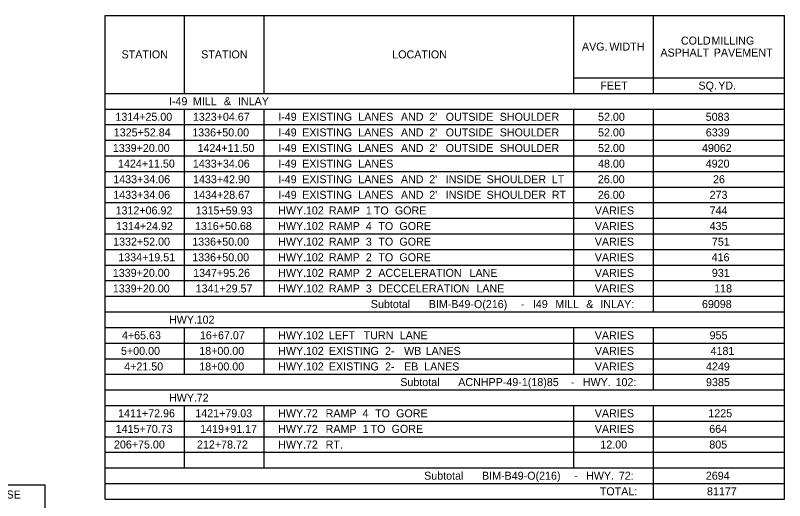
# Model space of a CAD drawing. Extents: x 1226561 to 1228164, y 151309 to 152305.
# Drawn here: x 1227627.4 to 1228108, y 151543 to 151846.2 of the extents above; entities that cross this region are included whole.
import ezdxf

# ---------------------------------------------------------------- set-up
doc = ezdxf.new("R2010")
doc.units = 0
doc.layers.add('R_Dimension', color=7, linetype='Continuous')

msp = doc.modelspace()

# ---------------------------------------------------------------- linework, layer by layer
at = {"layer": 'R_Dimension'}
for p, q in [((1227683.4, 151846.16), (1228108.01, 151846.16)), ((1227683.4, 151543.91), (1227683.4, 151846.16)), ((1227733.12, 151797.41), (1227733.12, 151846.16)), ((1227782.85, 151797.41), (1227782.85, 151846.16)), ((1227976.38, 151797.41), (1227976.38, 151846.16)), ((1228026.11, 151797.41), (1228026.11, 151846.16)), ((1228108.01, 151543.91), (1228108.01, 151846.16)), ((1227976.38, 151807.16), (1228108.01, 151807.16)), ((1227683.4, 151797.41), (1228108.01, 151797.41)), ((1227683.4, 151787.66), (1228108.01, 151787.66)), ((1227733.12, 151670.66), (1227733.12, 151787.66)), ((1227782.85, 151670.66), (1227782.85, 151787.66)), ((1227976.38, 151670.66), (1227976.38, 151787.66)), ((1228026.11, 151660.91), (1228026.11, 151787.66)), ((1227683.4, 151777.91), (1228108.01, 151777.91)), ((1227683.4, 151768.16), (1228108.01, 151768.16)), ((1227683.4, 151758.41), (1228108.01, 151758.41)), ((1227683.4, 151748.66), (1228108.01, 151748.66)), ((1227683.4, 151738.91), (1228108.01, 151738.91)), ((1227683.4, 151729.16), (1228108.01, 151729.16)), ((1227683.4, 151719.41), (1228108.01, 151719.41)), ((1227683.4, 151709.66), (1228108.01, 151709.66)), ((1227683.4, 151699.91), (1228108.01, 151699.91)), ((1227683.4, 151690.16), (1228108.01, 151690.16)), ((1227683.4, 151680.41), (1228108.01, 151680.41)), ((1227683.4, 151670.66), (1228108.01, 151670.66)), ((1227683.4, 151660.91), (1228108.01, 151660.91)), ((1227683.4, 151651.16), (1228108.01, 151651.16)), ((1227733.12, 151621.91), (1227733.12, 151651.16)), ((1227782.85, 151621.91), (1227782.85, 151651.16)), ((1227976.38, 151621.91), (1227976.38, 151651.16)), ((1228026.11, 151612.16), (1228026.11, 151651.16)), ((1227683.4, 151641.41), (1228108.01, 151641.41)), ((1227683.4, 151631.66), (1228108.01, 151631.66)), ((1227683.4, 151621.91), (1228108.01, 151621.91)), ((1227683.4, 151612.16), (1228108.01, 151612.16)), ((1227683.4, 151602.41), (1228108.01, 151602.41)), ((1227733.12, 151563.41), (1227733.12, 151602.41)), ((1227782.85, 151563.41), (1227782.85, 151602.41)), ((1227976.38, 151563.41), (1227976.38, 151602.41)), ((1228026.11, 151543.91), (1228026.11, 151602.41)), ((1227683.4, 151592.66), (1228108.01, 151592.66)), ((1227683.4, 151582.91), (1228108.01, 151582.91)), ((1227683.4, 151573.16), (1228108.01, 151573.16)), ((1227683.4, 151563.41), (1228108.01, 151563.41)), ((1227683.4, 151553.66), (1228108.01, 151553.66)), ((1227218.58, 151552.78), (1227646.11, 151552.78)), ((1227646.11, 151416.28), (1227646.11, 151552.78)), ((1227683.4, 151543.91), (1228108.01, 151543.91))]:
    msp.add_line(p, q, dxfattribs=at)

# ---------------------------------------------------------------- texts
for s, p in [('COLD', (1228043.22, 151827.91)), (' MILLING', (1228060.43, 151827.91)), ('AVG.', (1227981.38, 151824.16)), (' WIDTH', (1227996.66, 151824.16)), ('STATION', (1227693.75, 151819.29)), ('STATION', (1227743.48, 151819.29)), ('LOCATION', (1227862.86, 151819.29)), ('ASPHALT', (1228030.43, 151820.41)), (' PAVEMENT', (1228061.88, 151820.41)), ('FEET', (1227992.88, 151799.79)), ('SQ.', (1228054.17, 151799.79)), (' YD.', (1228064.64, 151799.79)), ('I-49', (1227723.37, 151790.04)), (' MILL', (1227736.48, 151790.04)), (' &', (1227755.81, 151790.04)), (' INLAY', (1227764.59, 151790.04)), ('1314+25.00', (1227689.89, 151780.29)), ('1323+04.67', (1227738.3, 151780.29)), ('I-49', (1227791.62, 151780.29)), (' EXISTING', (1227804.73, 151780.29)), (' LANES', (1227839.77, 151780.29)), (' AND', (1227866.42, 151780.29)), (" 2'", (1227884.14, 151780.29)), (' OUTSIDE', (1227894.42, 151780.29)), (' SHOULDER', (1227928.16, 151780.29)), ('52.00', (1227991.46, 151780.29)), ('5083', (1228058.71, 151780.29)), ('1325+52.84', (1227688.89, 151770.54)), ('1336+50.00', (1227737.89, 151770.54)), ('I-49', (1227791.62, 151770.54)), (' EXISTING', (1227804.73, 151770.54)), (' LANES', (1227839.77, 151770.54)), (' AND', (1227866.42, 151770.54)), (" 2'", (1227884.14, 151770.54)), (' OUTSIDE', (1227894.42, 151770.54)), (' SHOULDER', (1227928.16, 151770.54)), ('52.00', (1227991.46, 151770.54)), ('6339', (1228058.77, 151770.54)), ('1339+20.00', (1227688.28, 151760.79)), ('1424+11.50', (1227741.23, 151760.79)), ('I-49', (1227791.62, 151760.79)), (' EXISTING', (1227804.73, 151760.79)), (' LANES', (1227839.77, 151760.79)), (' AND', (1227866.42, 151760.79)), (" 2'", (1227884.14, 151760.79)), (' OUTSIDE', (1227894.42, 151760.79)), (' SHOULDER', (1227928.16, 151760.79)), ('52.00', (1227991.46, 151760.79)), ('49062', (1228056.35, 151760.79)), ('1424+11.50', (1227691.51, 151751.04)), ('1433+34.06', (1227738.28, 151751.04)), ('I-49', (1227791.62, 151751.04)), (' EXISTING', (1227804.73, 151751.04)), (' LANES', (1227839.77, 151751.04)), ('48.00', (1227991.46, 151751.04)), ('4920', (1228058.69, 151751.04)), ('1433+34.06', (1227688.55, 151741.29)), ('1433+42.90', (1227738.4, 151741.29)), ('I-49', (1227791.62, 151741.29)), (' EXISTING', (1227804.73, 151741.29)), (' LANES', (1227839.77, 151741.29)), (' AND', (1227866.42, 151741.29)), (" 2'", (1227884.14, 151741.29)), (' INSIDE', (1227894.42, 151741.29)), (' SHOULDER', (1227919.97, 151741.29)), (' LT', (1227960.68, 151741.29)), ('26.00', (1227991.34, 151741.29)), ('26', (1228063.26, 151741.29)), ('1433+34.06', (1227688.55, 151731.54)), ('1434+28.67', (1227738.5, 151731.54)), ('I-49', (1227791.62, 151731.54)), (' EXISTING', (1227804.73, 151731.54)), (' LANES', (1227839.77, 151731.54)), (' AND', (1227866.42, 151731.54)), (" 2'", (1227884.14, 151731.54)), (' INSIDE', (1227894.42, 151731.54)), (' SHOULDER', (1227919.97, 151731.54)), (' RT', (1227960.68, 151731.54)), ('26.00', (1227991.34, 151731.54)), ('273', (1228061.15, 151731.54)), ('1312+06.92', (1227689.99, 151721.79)), ('1315+59.93', (1227740.03, 151721.79)), ('HWY.', (1227791.62, 151721.79)), (' 102', (1227807.05, 151721.79)), (' RAMP', (1227821.42, 151721.79)), (' 1', (1227844.5, 151721.79)), (' TO', (1227849.5, 151721.79)), (' GORE', (1227862.64, 151721.79)), ('VARIES', (1227989.4, 151721.79)), ('744', (1228061.15, 151721.79)), ('1314+24.92', (1227690.31, 151712.04)), ('1316+50.68', (1227739.6, 151712.04)), ('HWY.', (1227791.62, 151712.04)), (' 102', (1227807.05, 151712.04)), (' RAMP', (1227821.42, 151712.04)), (' 4', (1227844.5, 151712.04)), (' TO', (1227852.33, 151712.04)), (' GORE', (1227865.48, 151712.04)), ('VARIES', (1227989.4, 151712.04)), ('435', (1228061.15, 151712.04)), ('1332+52.00', (1227688.48, 151702.29)), ('1336+50.00', (1227737.89, 151702.29)), (' 102', (1227807.05, 151702.29)), (' 3', (1227844.5, 151702.29)), (' TO', (1227852.33, 151702.29)), (' GORE', (1227865.48, 151702.29)), ('VARIES', (1227989.4, 151702.29)), ('HWY.', (1227791.62, 151702.29)), (' RAMP', (1227821.42, 151702.29)), ('751', (1228062.57, 151702.29)), ('1334+19.51', (1227691.72, 151692.54)), ('1336+50.00', (1227737.89, 151692.54)), ('HWY.', (1227791.62, 151692.54)), (' 102', (1227807.05, 151692.54)), (' RAMP', (1227821.42, 151692.54)), (' 2', (1227844.5, 151692.54)), (' TO', (1227852.33, 151692.54)), (' GORE', (1227865.48, 151692.54)), ('VARIES', (1227989.4, 151692.54)), ('416', (1228062.43, 151692.54)), ('1339+20.00', (1227688.28, 151682.79)), ('1347+95.26', (1227738.48, 151682.79)), ('HWY.', (1227791.62, 151682.79)), (' 102', (1227807.05, 151682.79)), (' RAMP', (1227821.42, 151682.79)), (' 2', (1227844.5, 151682.79)), (' ACCELERATION', (1227852.33, 151682.79)), (' LANE', (1227909.26, 151682.79)), ('VARIES', (1227989.4, 151682.79)), ('931', (1228062.57, 151682.79)), ('1339+20.00', (1227688.28, 151673.04)), ('1341+29.57', (1227740.03, 151673.04)), ('HWY.', (1227791.62, 151673.04)), (' 102', (1227807.05, 151673.04)), (' RAMP', (1227821.42, 151673.04)), (' 3', (1227844.5, 151673.04)), (' DECCELERATION', (1227852.33, 151673.04)), (' LANE', (1227913.59, 151673.04)), ('VARIES', (1227989.4, 151673.04)), ('118', (1228063.99, 151673.04)), ('Subtotal', (1227849.5, 151663.29)), (' BIM-B49-O(216)', (1227883.83, 151663.29)), (' -', (1227941.43, 151663.29)), (' I49', (1227948.87, 151663.29)), (' MILL', (1227962.89, 151663.29)), (' &', (1227982.22, 151663.29)), (' INLAY:', (1227991, 151663.29)), ('69098', (1228056.35, 151663.29)), ('HWY.', (1227723.37, 151653.54)), (' 102', (1227738.8, 151653.54)), ('4+65.63', (1227693.97, 151643.79)), ('16+67.07', (1227742.67, 151643.79)), ('HWY.', (1227791.62, 151643.79)), (' 102', (1227807.05, 151643.79)), (' LEFT', (1227821.42, 151643.79)), (' TURN', (1227843.16, 151643.79)), (' LANE', (1227865.68, 151643.79)), ('VARIES', (1227989.4, 151643.79)), ('955', (1228061.15, 151643.79)), ('5+00.00', (1227693.4, 151634.04)), ('18+00.00', (1227742.29, 151634.04)), ('HWY.', (1227791.62, 151634.04)), (' 102', (1227807.05, 151634.04)), (' EXISTING', (1227821.42, 151634.04)), (' 2-', (1227856.46, 151634.04)), (' WB', (1227868.39, 151634.04)), (' LANES', (1227881.86, 151634.04)), ('VARIES', (1227989.4, 151634.04)), ('4181', (1228061.74, 151634.04)), ('4+21.50', (1227695.4, 151624.29)), ('18+00.00', (1227742.29, 151624.29)), ('HWY.', (1227791.62, 151624.29)), (' 102', (1227807.05, 151624.29)), (' EXISTING', (1227821.42, 151624.29)), (' 2-', (1227856.46, 151624.29)), (' EB', (1227868.39, 151624.29)), (' LANES', (1227880.99, 151624.29)), ('VARIES', (1227989.4, 151624.29)), ('4249', (1228058.89, 151624.29)), ('Subtotal', (1227867.89, 151614.54)), (' ACNHPP-49-1(18)85', (1227902.22, 151614.54)), (' -', (1227972.65, 151614.54)), (' HWY.', (1227980.09, 151614.54)), (' 102:', (1228000.52, 151614.54)), ('9385', (1228058.91, 151614.54)), ('HWY.', (1227723.37, 151604.79)), (' 72', (1227738.8, 151604.79)), ('1411+72.96', (1227691.59, 151595.04)), ('1421+79.03', (1227739.83, 151595.04)), ('HWY.', (1227791.62, 151595.04)), (' 72', (1227807.05, 151595.04)), (' RAMP', (1227819.38, 151595.04)), (' 4', (1227842.45, 151595.04)), (' TO', (1227850.28, 151595.04)), (' GORE', (1227863.43, 151595.04)), ('VARIES', (1227989.4, 151595.04)), ('1225', (1228060.33, 151595.04)), ('1415+70.73', (1227690.11, 151585.29)), ('1419+91.17', (1227742.87, 151585.29)), ('HWY.', (1227791.62, 151585.29)), (' 72', (1227807.05, 151585.29)), (' RAMP', (1227819.38, 151585.29)), (' 1', (1227842.45, 151585.29)), (' TO', (1227847.45, 151585.29)), (' GORE', (1227860.6, 151585.29)), ('VARIES', (1227989.4, 151585.29)), ('664', (1228060.92, 151585.29)), ('206+75.00', (1227688.99, 151575.54)), ('212+78.72', (1227740.86, 151575.54)), ('HWY.', (1227791.62, 151575.54)), (' 72', (1227807.05, 151575.54)), (' RT.', (1227819.38, 151575.54)), ('12.00', (1227992.88, 151575.54)), ('805', (1228060.96, 151575.54)), ('Subtotal', (1227882.77, 151556.04)), (' BIM-B49-O(216)', (1227917.1, 151556.04)), (' HWY.', (1227982.14, 151556.04)), (' 72:', (1228002.57, 151556.04)), ('2694', (1228058.79, 151556.04)), (' -', (1227974.7, 151556.04)), (' BASE', (1227611.1, 151544.28)), ('TOTAL:', (1227992.53, 151546.29)), ('81177', (1228059.5, 151546.29))]:
    msp.add_text(s, height=5, dxfattribs=at).set_placement(p)

doc.saveas('drawing.dxf')
